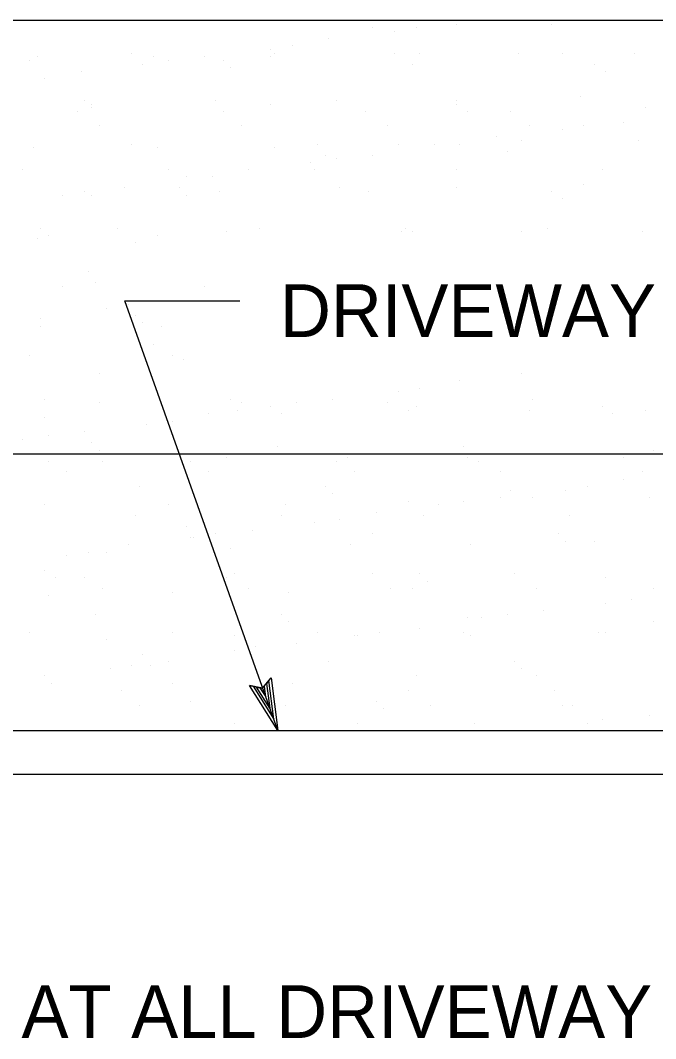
# Model space of a CAD drawing. Extents: x -118779 to -116979, y -104389 to -102939.
# Drawn here: x -118334.6 to -118262.3, y -103158.8 to -103042.9 of the extents above; entities that cross this region are included whole.
import ezdxf

# ---------------------------------------------------------------- set-up
doc = ezdxf.new("R2010")
doc.units = 0
for name, color, linetype in [('G-MARK', 7, 'Continuous'), ('G-TEXT', 7, 'Continuous'), ('Misc CnstDet(22)', 7, 'Continuous')]:
    doc.layers.add(name, color=color, linetype=linetype)

msp = doc.modelspace()

# ---------------------------------------------------------------- linework, layer by layer
at = {"layer": 'G-MARK'}
msp.add_lwpolyline([(-118305.27, -103123.73), (-118322.69, -103074.79), (-118309.59, -103074.79)], dxfattribs=at)
at = {"layer": 'G-TEXT'}
msp.add_lwpolyline([(-118306.01, -103117.73), (-118305.27, -103123.73), (-118308.48, -103118.61), (-118308.08, -103118.69), (-118305.73, -103122.44), (-118306.27, -103118.04), (-118306.53, -103118.36), (-118306.18, -103121.17), (-118307.69, -103118.77), (-118307.29, -103118.85), (-118306.63, -103119.89), (-118306.79, -103118.67), (-118306.99, -103118.91), (-118308.48, -103118.61), (-118306.99, -103118.91)], close=True, dxfattribs=at)
at = {"layer": 'Misc CnstDet(22)'}
for p, q in [((-118294.48, -103043.68), (-118294.48, -103043.68)), ((-118289.5, -103043.68), (-118289.5, -103043.68)), ((-118284.94, -103043.27), (-118284.94, -103043.27)), ((-118274.16, -103043.27), (-118274.16, -103043.27)), ((-118291.99, -103044.1), (-118291.99, -103044.1)), ((-118303.61, -103045.76), (-118303.61, -103045.76)), ((-118299.46, -103044.93), (-118299.46, -103044.93)), ((-118332.64, -103047), (-118332.64, -103047)), ((-118321.86, -103046.59), (-118321.86, -103046.59)), ((-118319.37, -103047), (-118319.37, -103047)), ((-118313.56, -103047), (-118313.56, -103047)), ((-118306.09, -103046.17), (-118306.09, -103046.17)), ((-118306.09, -103047), (-118306.09, -103047)), ((-118305.68, -103046.59), (-118305.68, -103046.59)), ((-118291.99, -103046.59), (-118291.99, -103046.59)), ((-118289.09, -103046.59), (-118289.09, -103046.59)), ((-118277.89, -103046.59), (-118277.89, -103046.59)), ((-118272.91, -103046.59), (-118272.91, -103046.59)), ((-118264.62, -103046.59), (-118264.62, -103046.59)), ((-118333.47, -103047.42), (-118333.47, -103047.42)), ((-118320.61, -103047.83), (-118320.61, -103047.83)), ((-118317.71, -103047.42), (-118317.71, -103047.42)), ((-118311.49, -103047.42), (-118311.49, -103047.42)), ((-118310.66, -103048.25), (-118310.66, -103048.25)), ((-118289.92, -103047.83), (-118289.92, -103047.83)), ((-118269.18, -103047.83), (-118269.18, -103047.83)), ((-118331.81, -103049.49), (-118331.81, -103049.49)), ((-118327.66, -103048.66), (-118327.66, -103048.66)), ((-118267.94, -103048.66), (-118267.94, -103048.66)), ((-118270.84, -103051.56), (-118270.84, -103051.56)), ((-118327.25, -103051.98), (-118327.25, -103051.98)), ((-118326.42, -103052.39), (-118326.42, -103052.39)), ((-118326.42, -103052.81), (-118326.42, -103052.81)), ((-118312.32, -103051.98), (-118312.32, -103051.98)), ((-118306.09, -103052.39), (-118306.09, -103052.39)), ((-118298.63, -103051.98), (-118298.63, -103051.98)), ((-118284.94, -103051.98), (-118284.94, -103051.98)), ((-118284.94, -103052.39), (-118284.94, -103052.39)), ((-118263.37, -103052.81), (-118263.37, -103052.81)), ((-118328.08, -103053.22), (-118328.08, -103053.22)), ((-118311.49, -103053.22), (-118311.49, -103053.22)), ((-118295.31, -103053.22), (-118295.31, -103053.22)), ((-118283.7, -103053.22), (-118283.7, -103053.22)), ((-118278.72, -103053.22), (-118278.72, -103053.22)), ((-118325.59, -103054.88), (-118325.59, -103054.88)), ((-118309.41, -103054.88), (-118309.41, -103054.88)), ((-118292.82, -103054.88), (-118292.82, -103054.88)), ((-118276.65, -103054.88), (-118276.65, -103054.88)), ((-118272.91, -103055.3), (-118272.91, -103055.3)), ((-118270.43, -103054.88), (-118270.43, -103054.88)), ((-118265.86, -103054.47), (-118265.86, -103054.47)), ((-118280.38, -103056.13), (-118280.38, -103056.13)), ((-118333.05, -103057.37), (-118333.05, -103057.37)), ((-118321.86, -103056.96), (-118321.86, -103056.96)), ((-118318.95, -103057.37), (-118318.95, -103057.37)), ((-118305.68, -103057.37), (-118305.68, -103057.37)), ((-118300.7, -103056.96), (-118300.7, -103056.96)), ((-118291.58, -103056.96), (-118291.58, -103056.96)), ((-118287.43, -103056.96), (-118287.43, -103056.96)), ((-118284.53, -103056.96), (-118284.53, -103056.96)), ((-118277.48, -103056.54), (-118277.48, -103056.54)), ((-118264.2, -103056.54), (-118264.2, -103056.54)), ((-118299.87, -103058.2), (-118299.87, -103058.2)), ((-118298.63, -103058.62), (-118298.63, -103058.62)), ((-118294.48, -103058.2), (-118294.48, -103058.2)), ((-118279.14, -103057.79), (-118279.14, -103057.79)), ((-118334.3, -103059.86), (-118334.3, -103059.86)), ((-118317.71, -103059.86), (-118317.71, -103059.86)), ((-118308.58, -103059.86), (-118308.58, -103059.86)), ((-118301.53, -103059.03), (-118301.53, -103059.03)), ((-118301.12, -103059.86), (-118301.12, -103059.86)), ((-118284.94, -103059.86), (-118284.94, -103059.86)), ((-118268.35, -103059.86), (-118268.35, -103059.86)), ((-118315.63, -103060.69), (-118315.63, -103060.69)), ((-118312.73, -103060.69), (-118312.73, -103060.69)), ((-118322.69, -103061.93), (-118322.69, -103061.93)), ((-118316.46, -103061.93), (-118316.46, -103061.93)), ((-118298.21, -103061.93), (-118298.21, -103061.93)), ((-118284.94, -103061.93), (-118284.94, -103061.93)), ((-118270.43, -103061.52), (-118270.43, -103061.52)), ((-118329.74, -103062.76), (-118329.74, -103062.76)), ((-118327.25, -103062.35), (-118327.25, -103062.35)), ((-118326.42, -103062.76), (-118326.42, -103062.76)), ((-118315.63, -103062.76), (-118315.63, -103062.76)), ((-118311.9, -103062.35), (-118311.9, -103062.35)), ((-118294.9, -103062.35), (-118294.9, -103062.35)), ((-118274.16, -103062.35), (-118274.16, -103062.35)), ((-118272.91, -103063.18), (-118272.91, -103063.18)), ((-118332.22, -103066.5), (-118332.22, -103066.5)), ((-118323.51, -103066.5), (-118323.51, -103066.5)), ((-118307.34, -103066.5), (-118307.34, -103066.5)), ((-118290.75, -103066.5), (-118290.75, -103066.5)), ((-118274.57, -103066.5), (-118274.57, -103066.5)), ((-118332.64, -103067.74), (-118332.64, -103067.74)), ((-118331.4, -103067.33), (-118331.4, -103067.33)), ((-118318.95, -103067.33), (-118318.95, -103067.33)), ((-118311.07, -103066.91), (-118311.07, -103066.91)), ((-118291.16, -103066.91), (-118291.16, -103066.91)), ((-118289.92, -103066.91), (-118289.92, -103066.91)), ((-118277.48, -103066.91), (-118277.48, -103066.91)), ((-118263.79, -103066.91), (-118263.79, -103066.91)), ((-118321.44, -103068.15), (-118321.44, -103068.15)), ((-118326.83, -103071.47), (-118326.83, -103071.47)), ((-118329.74, -103073.13), (-118329.74, -103073.13)), ((-118326, -103072.72), (-118326, -103072.72)), ((-118313.56, -103073.13), (-118313.56, -103073.13)), ((-118317.71, -103074.79), (-118317.71, -103074.79)), ((-118324.76, -103075.62), (-118324.76, -103075.62)), ((-118322.27, -103075.21), (-118322.27, -103075.21)), ((-118332.22, -103076.86), (-118332.22, -103076.86)), ((-118321.44, -103076.45), (-118321.44, -103076.45)), ((-118320.61, -103077.28), (-118320.61, -103077.28)), ((-118332.22, -103077.69), (-118332.22, -103077.69)), ((-118318.54, -103077.69), (-118318.54, -103077.69)), ((-118319.37, -103079.77), (-118319.37, -103079.77)), ((-118333.47, -103081.01), (-118333.47, -103081.01)), ((-118317.29, -103081.01), (-118317.29, -103081.01)), ((-118316.05, -103081.43), (-118316.05, -103081.43)), ((-118325.59, -103083.09), (-118325.59, -103083.09)), ((-118277.48, -103083.09), (-118277.48, -103083.09)), ((-118284.53, -103083.92), (-118284.53, -103083.92)), ((-118291.58, -103085.16), (-118291.58, -103085.16)), ((-118289.09, -103084.75), (-118289.09, -103084.75)), ((-118331.81, -103085.99), (-118331.81, -103085.99)), ((-118325.59, -103086.4), (-118325.59, -103086.4)), ((-118310.66, -103085.99), (-118310.66, -103085.99)), ((-118309.41, -103086.4), (-118309.41, -103086.4)), ((-118303.19, -103086.4), (-118303.19, -103086.4)), ((-118299.04, -103085.99), (-118299.04, -103085.99)), ((-118292.82, -103086.4), (-118292.82, -103086.4)), ((-118276.23, -103085.99), (-118276.23, -103085.99)), ((-118318.12, -103087.65), (-118318.12, -103087.65)), ((-118313.15, -103087.65), (-118313.15, -103087.65)), ((-118309.83, -103087.23), (-118309.83, -103087.23)), ((-118306.09, -103086.82), (-118306.09, -103086.82)), ((-118304.85, -103087.65), (-118304.85, -103087.65)), ((-118290.33, -103087.23), (-118290.33, -103087.23)), ((-118289.5, -103086.82), (-118289.5, -103086.82)), ((-118276.65, -103087.23), (-118276.65, -103087.23)), ((-118268.35, -103086.82), (-118268.35, -103086.82)), ((-118267.11, -103087.65), (-118267.11, -103087.65)), ((-118263.37, -103087.23), (-118263.37, -103087.23)), ((-118331.81, -103088.06), (-118331.81, -103088.06)), ((-118320.2, -103088.89), (-118320.2, -103088.89)), ((-118317.29, -103088.48), (-118317.29, -103088.48)), ((-118327.25, -103089.72), (-118327.25, -103089.72)), ((-118334.3, -103090.55), (-118334.3, -103090.55)), ((-118331.4, -103090.14), (-118331.4, -103090.14)), ((-118326.42, -103090.97), (-118326.42, -103090.97)), ((-118325.59, -103091.8), (-118325.59, -103091.8)), ((-118305.27, -103091.38), (-118305.27, -103091.38)), ((-118284.11, -103091.38), (-118284.11, -103091.38)), ((-118283.28, -103092.21), (-118283.28, -103092.21)), ((-118269.6, -103092.21), (-118269.6, -103092.21)), ((-118262.54, -103091.8), (-118262.54, -103091.8)), ((-118331.4, -103093.04), (-118331.4, -103093.04)), ((-118325.17, -103093.04), (-118325.17, -103093.04)), ((-118315.22, -103093.04), (-118315.22, -103093.04)), ((-118311.07, -103092.63), (-118311.07, -103092.63)), ((-118298.63, -103093.04), (-118298.63, -103093.04)), ((-118297.38, -103092.63), (-118297.38, -103092.63)), ((-118283.7, -103092.63), (-118283.7, -103092.63)), ((-118282.45, -103093.04), (-118282.45, -103093.04)), ((-118265.86, -103092.63), (-118265.86, -103092.63)), ((-118329.32, -103094.28), (-118329.32, -103094.28)), ((-118313.15, -103094.28), (-118313.15, -103094.28)), ((-118296.56, -103094.28), (-118296.56, -103094.28)), ((-118279.96, -103094.28), (-118279.96, -103094.28)), ((-118263.79, -103094.28), (-118263.79, -103094.28)), ((-118265.86, -103095.11), (-118265.86, -103095.11)), ((-118321.03, -103095.94), (-118321.03, -103095.94)), ((-118299.87, -103095.94), (-118299.87, -103095.94)), ((-118299.04, -103096.77), (-118299.04, -103096.77)), ((-118278.72, -103096.36), (-118278.72, -103096.36)), ((-118272.5, -103096.36), (-118272.5, -103096.36)), ((-118270.01, -103095.94), (-118270.01, -103095.94)), ((-118331.81, -103098.02), (-118331.81, -103098.02)), ((-118317.71, -103098.02), (-118317.71, -103098.02)), ((-118304.44, -103098.02), (-118304.44, -103098.02)), ((-118290.33, -103097.6), (-118290.33, -103097.6)), ((-118287.02, -103098.02), (-118287.02, -103098.02)), ((-118284.11, -103097.6), (-118284.11, -103097.6)), ((-118279.96, -103097.19), (-118279.96, -103097.19)), ((-118276.23, -103097.19), (-118276.23, -103097.19)), ((-118262.96, -103097.19), (-118262.96, -103097.19)), ((-118321.44, -103099.26), (-118321.44, -103099.26)), ((-118304.85, -103099.26), (-118304.85, -103099.26)), ((-118294.07, -103098.85), (-118294.07, -103098.85)), ((-118288.67, -103099.26), (-118288.67, -103099.26)), ((-118272.08, -103099.26), (-118272.08, -103099.26)), ((-118315.63, -103100.51), (-118315.63, -103100.51)), ((-118301.12, -103100.09), (-118301.12, -103100.09)), ((-118298.21, -103099.68), (-118298.21, -103099.68)), ((-118312.32, -103101.34), (-118312.32, -103101.34)), ((-118308.17, -103100.92), (-118308.17, -103100.92)), ((-118294.48, -103101.34), (-118294.48, -103101.34)), ((-118273.33, -103101.34), (-118273.33, -103101.34)), ((-118322.27, -103102.58), (-118322.27, -103102.58)), ((-118315.22, -103101.75), (-118315.22, -103101.75)), ((-118314.8, -103101.75), (-118314.8, -103101.75)), ((-118296.97, -103102.58), (-118296.97, -103102.58)), ((-118283.28, -103102.58), (-118283.28, -103102.58)), ((-118272.5, -103102.17), (-118272.5, -103102.17)), ((-118269.18, -103102.17), (-118269.18, -103102.17)), ((-118329.32, -103103.82), (-118329.32, -103103.82)), ((-118326.83, -103103.41), (-118326.83, -103103.41)), ((-118324.76, -103103.41), (-118324.76, -103103.41)), ((-118310.66, -103102.99), (-118310.66, -103102.99)), ((-118331.81, -103105.48), (-118331.81, -103105.48)), ((-118330.57, -103106.31), (-118330.57, -103106.31)), ((-118327.25, -103106.31), (-118327.25, -103106.31)), ((-118311.07, -103106.31), (-118311.07, -103106.31)), ((-118310.24, -103105.9), (-118310.24, -103105.9)), ((-118294.48, -103105.9), (-118294.48, -103105.9)), ((-118289.09, -103105.9), (-118289.09, -103105.9)), ((-118278.31, -103105.9), (-118278.31, -103105.9)), ((-118267.94, -103106.31), (-118267.94, -103106.31)), ((-118288.26, -103106.73), (-118288.26, -103106.73)), ((-118331.4, -103108.39), (-118331.4, -103108.39)), ((-118325.17, -103107.56), (-118325.17, -103107.56)), ((-118317.29, -103107.97), (-118317.29, -103107.97)), ((-118308.58, -103107.56), (-118308.58, -103107.56)), ((-118304.02, -103107.97), (-118304.02, -103107.97)), ((-118292.41, -103107.56), (-118292.41, -103107.56)), ((-118289.92, -103107.56), (-118289.92, -103107.56)), ((-118275.82, -103107.56), (-118275.82, -103107.56)), ((-118275.82, -103107.56), (-118275.82, -103107.56)), ((-118262.54, -103107.56), (-118262.54, -103107.56)), ((-118267.94, -103109.22), (-118267.94, -103109.22)), ((-118265.03, -103108.8), (-118265.03, -103108.8)), ((-118326, -103110.46), (-118326, -103110.46)), ((-118304.85, -103110.46), (-118304.85, -103110.46)), ((-118283.7, -103110.88), (-118283.7, -103110.88)), ((-118282.04, -103110.88), (-118282.04, -103110.88)), ((-118279.14, -103110.46), (-118279.14, -103110.46)), ((-118274.99, -103110.05), (-118274.99, -103110.05)), ((-118304.02, -103111.29), (-118304.02, -103111.29)), ((-118262.54, -103111.29), (-118262.54, -103111.29)), ((-118333.47, -103112.53), (-118333.47, -103112.53)), ((-118317.29, -103112.53), (-118317.29, -103112.53)), ((-118310.24, -103112.95), (-118310.24, -103112.95)), ((-118300.7, -103112.53), (-118300.7, -103112.53)), ((-118296.56, -103112.95), (-118296.56, -103112.95)), ((-118296.14, -103112.95), (-118296.14, -103112.95)), ((-118293.65, -103112.53), (-118293.65, -103112.53)), ((-118289.09, -103112.12), (-118289.09, -103112.12)), ((-118284.11, -103112.53), (-118284.11, -103112.53)), ((-118283.28, -103112.95), (-118283.28, -103112.95)), ((-118268.77, -103112.53), (-118268.77, -103112.53)), ((-118267.94, -103112.53), (-118267.94, -103112.53)), ((-118324.76, -103113.36), (-118324.76, -103113.36)), ((-118307.75, -103114.19), (-118307.75, -103114.19)), ((-118303.19, -103113.78), (-118303.19, -103113.78)), ((-118320.61, -103115.02), (-118320.61, -103115.02)), ((-118310.24, -103114.61), (-118310.24, -103114.61)), ((-118324.34, -103116.68), (-118324.34, -103116.68)), ((-118321.86, -103116.27), (-118321.86, -103116.27)), ((-118319.78, -103116.27), (-118319.78, -103116.27)), ((-118317.71, -103115.85), (-118317.71, -103115.85)), ((-118299.46, -103115.85), (-118299.46, -103115.85)), ((-118278.31, -103115.85), (-118278.31, -103115.85)), ((-118277.48, -103116.68), (-118277.48, -103116.68)), ((-118331.81, -103117.51), (-118331.81, -103117.51)), ((-118289.5, -103117.51), (-118289.5, -103117.51)), ((-118275.82, -103117.51), (-118275.82, -103117.51)), ((-118330.98, -103118.34), (-118330.98, -103118.34)), ((-118317.29, -103118.34), (-118317.29, -103118.34)), ((-118303.61, -103118.34), (-118303.61, -103118.34)), ((-118323.1, -103119.17), (-118323.1, -103119.17)), ((-118306.51, -103119.17), (-118306.51, -103119.17)), ((-118290.33, -103119.17), (-118290.33, -103119.17)), ((-118273.74, -103119.17), (-118273.74, -103119.17)), ((-118321.03, -103120.83), (-118321.03, -103120.83)), ((-118315.22, -103120.41), (-118315.22, -103120.41)), ((-118304.44, -103120.83), (-118304.44, -103120.83)), ((-118294.07, -103120.41), (-118294.07, -103120.41)), ((-118293.24, -103121.24), (-118293.24, -103121.24)), ((-118287.85, -103120.83), (-118287.85, -103120.83)), ((-118272.91, -103120.83), (-118272.91, -103120.83)), ((-118271.67, -103120.83), (-118271.67, -103120.83)), ((-118268.35, -103122.49), (-118268.35, -103122.49)), ((-118262.96, -103122.07), (-118262.96, -103122.07)), ((-118310.24, -103122.9), (-118310.24, -103122.9)), ((-118296.14, -103122.9), (-118296.14, -103122.9)), ((-118282.87, -103122.9), (-118282.87, -103122.9)), ((-118270.01, -103122.9), (-118270.01, -103122.9)), ((-118324.34, -103123.73), (-118324.34, -103123.73))]:
    msp.add_line(p, q, dxfattribs=at)
for points in [[(-118410.62, -103042.85), (-118094.15, -103042.85)], [(-118396.1, -103092.21), (-118094.15, -103092.21)], [(-118386.97, -103123.73), (-118094.15, -103123.73)], [(-118385.73, -103128.71), (-118094.15, -103128.71)]]:
    msp.add_lwpolyline(points, dxfattribs=at)

# ---------------------------------------------------------------- texts
for s, p in [('DRIVEWAY', (-118305.01, -103078.91)), ('AT ALL DRIVEWAY LOCATIONS', (-118334.43, -103158.73))]:
    msp.add_text(s, height=6, dxfattribs=at).set_placement(p)

doc.saveas('drawing.dxf')
